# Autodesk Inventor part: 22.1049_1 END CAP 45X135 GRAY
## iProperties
Created: 2007-01
Part Number: 22.1049_1 END CAP 45X135 GRAY
Document SubType Name: Modeling
Designer: Andy Moles
Material: ABS Plastic
Density: 1.06 g/cm^3
Author: Andy Moles
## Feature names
1. Extrusion1
2. Fillet1
3. Fillet2
4. Extrusion3
5. Fillet3
